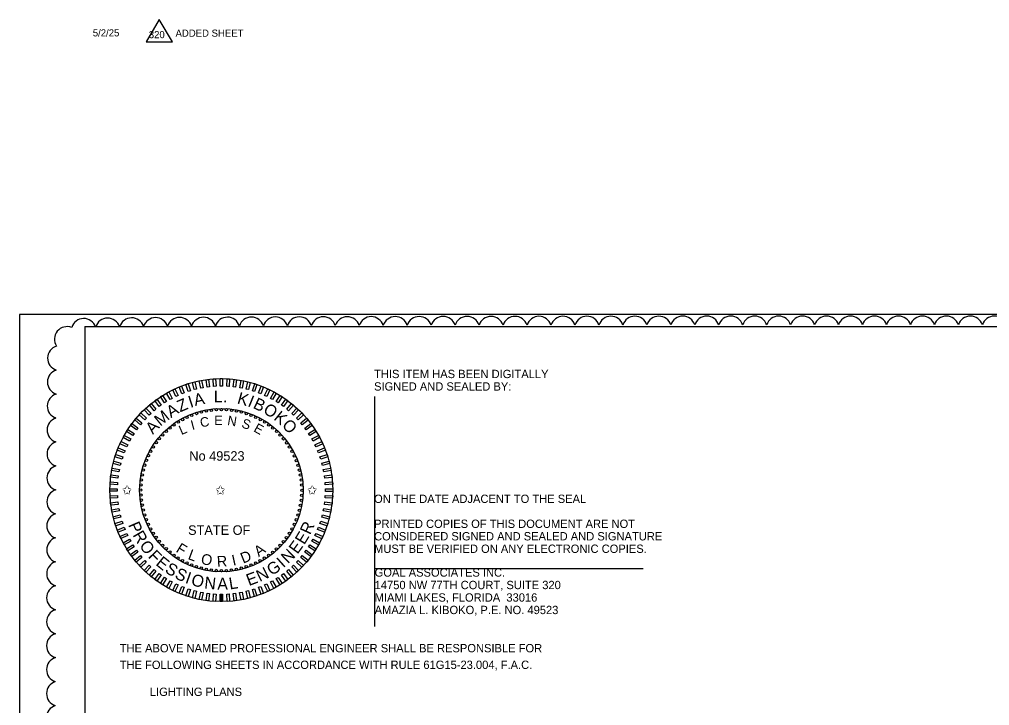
# Model space of a CAD drawing. Extents: x -811.2 to -755.6, y -2295.2 to -2235.1.
# Drawn here: x -783.91 to -775.75, y -2275.63 to -2269.86 of the extents above; entities that cross this region are included whole.
import ezdxf

# ---------------------------------------------------------------- set-up
doc = ezdxf.new("R2010")
doc.units = 0
for name, color, linetype in [('Cloud_dp', 7, 'Continuous'), ('Logo_dp', 7, 'Continuous'), ('NonPlottingEle_dp', 7, 'Continuous'), ('PlotBorder_dp', 7, 'Continuous'), ('ScratchEle_dp', 7, 'Continuous'), ('SheetBorder_dp', 7, 'Continuous'), ('TextMinor', 7, 'Continuous'), ('TextMisc', 7, 'Continuous')]:
    doc.layers.add(name, color=color, linetype=linetype)

msp = doc.modelspace()

# ---------------------------------------------------------------- linework, layer by layer
at = {"layer": 'Cloud_dp'}
msp.add_lwpolyline([(-782.7321, -2269.8629), (-782.8398, -2270.051), (-782.6192, -2270.051)], close=True, dxfattribs=at)
for centre, start, end in [((-783.3652, -2272.4837), 18.59454, 163.59454), ((-783.1638, -2272.4805), 18.21421, 163.21421), ((-782.9624, -2272.4783), 18.04696, 163.04696), ((-782.7609, -2272.4766), 17.94666, 162.94666), ((-782.5594, -2272.4751), 17.87787, 162.87787), ((-782.3579, -2272.4739), 17.82689, 162.82689), ((-782.1564, -2272.4728), 17.78716, 162.78716), ((-781.9548, -2272.4719), 17.75505, 162.75505), ((-781.7533, -2272.471), 17.72841, 162.72841), ((-781.5518, -2272.4702), 17.70584, 162.70584), ((-781.3502, -2272.4696), 17.6864, 162.6864), ((-781.1487, -2272.4689), 17.66942, 162.66942), ((-780.9472, -2272.4684), 17.65443, 162.65443), ((-780.7456, -2272.4678), 17.64106, 162.64106), ((-780.5441, -2272.4674), 17.62905, 162.62905), ((-780.3425, -2272.4669), 17.61817, 162.61817), ((-780.141, -2272.4665), 17.60826, 162.60826), ((-779.9394, -2272.4662), 17.59919, 162.59919), ((-779.7379, -2272.4658), 17.59084, 162.59084), ((-779.5364, -2272.4655), 17.58312, 162.58312), ((-779.3348, -2272.4653), 17.57595, 162.57595), ((-779.1333, -2272.465), 17.56928, 162.56928), ((-778.9317, -2272.4648), 17.56305, 162.56305), ((-778.7302, -2272.4646), 17.55721, 162.55721), ((-778.5286, -2272.4644), 17.55172, 162.55172), ((-778.3271, -2272.4642), 17.54655, 162.54655), ((-778.1255, -2272.464), 17.54167, 162.54167), ((-777.924, -2272.4639), 17.53705, 162.53705), ((-777.7224, -2272.4638), 17.53267, 162.53267), ((-777.5209, -2272.4637), 17.52851, 162.52851), ((-777.3194, -2272.4636), 17.52455, 162.52455), ((-777.1178, -2272.4635), 17.52079, 162.52079), ((-776.9163, -2272.4634), 17.51719, 162.51719), ((-776.7147, -2272.4634), 17.51375, 162.51375), ((-776.5132, -2272.4633), 17.51046, 162.51046), ((-776.3116, -2272.4633), 17.50731, 162.50731), ((-776.1101, -2272.4633), 17.50428, 162.50428), ((-775.9085, -2272.4633), 17.50138, 162.50138), ((-775.707, -2272.4633), 17.5, 162.5), ((-783.5053, -2272.5521), 68.43954, 213.43954), ((-783.563, -2272.7115), 106.80445, 251.80445), ((-783.565, -2272.9129), 107.04367, 252.04367), ((-783.5664, -2273.1144), 107.15618, 252.15618), ((-783.5675, -2273.3159), 107.22533, 252.22533), ((-783.5684, -2273.5174), 107.27338, 252.27338), ((-783.5691, -2273.719), 107.30928, 252.30928), ((-783.5697, -2273.9205), 107.33743, 252.33743), ((-783.5703, -2274.122), 107.36027, 252.36027), ((-783.5707, -2274.3236), 107.37928, 252.37928), ((-783.5711, -2274.5251), 107.39543, 252.39543), ((-783.5715, -2274.7267), 107.40937, 252.40937), ((-783.5717, -2274.9282), 107.42156, 252.42156), ((-783.572, -2275.1297), 107.43234, 252.43234), ((-783.5722, -2275.3313), 107.44197, 252.44197), ((-783.5724, -2275.5328), 107.45063, 252.45063), ((-783.5726, -2275.7344), 107.45847, 252.45847)]:
    msp.add_arc(centre, 0.1057, start, end, dxfattribs=at)
at = {"layer": 'Logo_dp'}
for p, q in [((-782.2178, -2274.759), (-782.218, -2274.6965)), ((-782.2078, -2274.759), (-782.208, -2274.6965)), ((-782.1978, -2274.759), (-782.198, -2274.6965))]:
    msp.add_line(p, q, dxfattribs=at)
for points in [[(-782.4685, -2272.9862), (-782.4877, -2272.9924), (-782.507, -2272.933), (-782.4878, -2272.9268)], [(-782.4156, -2272.9714), (-782.4351, -2272.9765), (-782.4506, -2272.916), (-782.4311, -2272.911)], [(-782.3618, -2272.9601), (-782.3816, -2272.9638), (-782.3933, -2272.9025), (-782.3735, -2272.8987)], [(-782.3074, -2272.9521), (-782.3274, -2272.9546), (-782.3352, -2272.8927), (-782.3152, -2272.8902)], [(-782.2526, -2272.9476), (-782.2727, -2272.9488), (-782.2767, -2272.8865), (-782.2565, -2272.8852)], [(-782.1976, -2272.9465), (-782.2178, -2272.9465), (-782.2178, -2272.884), (-782.1976, -2272.884)], [(-782.1427, -2272.9488), (-782.1629, -2272.9476), (-782.1589, -2272.8853), (-782.1388, -2272.8865)], [(-782.088, -2272.9547), (-782.1081, -2272.9521), (-782.1002, -2272.8902), (-782.0802, -2272.8927)], [(-782.0338, -2272.9639), (-782.0537, -2272.9601), (-782.042, -2272.8988), (-782.0221, -2272.9026)], [(-781.9803, -2272.9765), (-781.9999, -2272.9715), (-781.9844, -2272.911), (-781.9648, -2272.916)], [(-781.9277, -2272.9925), (-781.9469, -2272.9862), (-781.9276, -2272.9268), (-781.9084, -2272.9331)], [(-782.6204, -2273.0498), (-782.6381, -2273.0595), (-782.6682, -2273.0048), (-782.6505, -2272.9951)], [(-782.5712, -2273.0254), (-782.5894, -2273.034), (-782.616, -2272.9775), (-782.5978, -2272.9689)], [(-782.5205, -2273.0042), (-782.5392, -2273.0116), (-782.5622, -2272.9536), (-782.5434, -2272.9461)], [(-781.8762, -2273.0117), (-781.895, -2273.0042), (-781.872, -2272.9462), (-781.8532, -2272.9536)], [(-781.826, -2273.0341), (-781.8443, -2273.0255), (-781.8177, -2272.969), (-781.7994, -2272.9776)], [(-781.7773, -2273.0596), (-781.795, -2273.0499), (-781.7649, -2272.9952), (-781.7473, -2273.0049)], [(-782.7139, -2273.1076), (-782.7302, -2273.1195), (-782.7669, -2273.069), (-782.7506, -2273.0571)], [(-782.6681, -2273.0772), (-782.6851, -2273.0881), (-782.7186, -2273.0353), (-782.7015, -2273.0245)], [(-781.7303, -2273.0882), (-781.7474, -2273.0773), (-781.7139, -2273.0246), (-781.6969, -2273.0354)], [(-781.6852, -2273.1196), (-781.7016, -2273.1077), (-781.6649, -2273.0572), (-781.6485, -2273.0691)], [(-782.8387, -2273.2151), (-782.8525, -2273.2298), (-782.898, -2273.1871), (-782.8842, -2273.1723)], [(-782.7994, -2273.1767), (-782.8141, -2273.1905), (-782.8568, -2273.145), (-782.8421, -2273.1311)], [(-782.7577, -2273.1408), (-782.7733, -2273.1537), (-782.8131, -2273.1055), (-782.7975, -2273.0927)], [(-781.6422, -2273.1538), (-781.6578, -2273.1409), (-781.618, -2273.0928), (-781.6024, -2273.1057)], [(-781.6014, -2273.1906), (-781.6161, -2273.1768), (-781.5734, -2273.1313), (-781.5586, -2273.1451)], [(-781.563, -2273.2299), (-781.5768, -2273.2152), (-781.5313, -2273.1725), (-781.5175, -2273.1872)], [(-782.8755, -2273.2559), (-782.8884, -2273.2714), (-782.9365, -2273.2316), (-782.9237, -2273.2161)], [(-781.5271, -2273.2716), (-781.54, -2273.256), (-781.4919, -2273.2162), (-781.479, -2273.2318)], [(-782.9412, -2273.344), (-782.952, -2273.3611), (-783.0047, -2273.3276), (-782.9939, -2273.3106)], [(-782.9097, -2273.2989), (-782.9216, -2273.3153), (-782.9721, -2273.2786), (-782.9603, -2273.2622)], [(-781.4939, -2273.3154), (-781.5058, -2273.2991), (-781.4553, -2273.2624), (-781.4434, -2273.2787)], [(-781.4635, -2273.3612), (-781.4744, -2273.3442), (-781.4216, -2273.3107), (-781.4108, -2273.3278)], [(-782.9952, -2273.4397), (-783.0038, -2273.458), (-783.0603, -2273.4314), (-783.0517, -2273.4131)], [(-782.9697, -2273.391), (-782.9794, -2273.4087), (-783.0341, -2273.3786), (-783.0244, -2273.361)], [(-781.4361, -2273.4089), (-781.4458, -2273.3912), (-781.3911, -2273.3611), (-781.3814, -2273.3788)], [(-781.4117, -2273.4582), (-781.4203, -2273.4399), (-781.3638, -2273.4133), (-781.3552, -2273.4316)], [(-783.0176, -2273.4899), (-783.0251, -2273.5087), (-783.0831, -2273.4857), (-783.0757, -2273.4669)], [(-781.3905, -2273.5089), (-781.3979, -2273.4901), (-781.3399, -2273.4671), (-781.3324, -2273.4859)], [(-783.0528, -2273.594), (-783.0578, -2273.6136), (-783.1183, -2273.5981), (-783.1133, -2273.5785)], [(-783.0369, -2273.5414), (-783.0431, -2273.5606), (-783.1025, -2273.5413), (-783.0963, -2273.5221)], [(-781.3725, -2273.5608), (-781.3787, -2273.5416), (-781.3193, -2273.5223), (-781.3131, -2273.5415)], [(-781.3577, -2273.6138), (-781.3628, -2273.5942), (-781.3023, -2273.5787), (-781.2973, -2273.5982)], [(-783.0654, -2273.6475), (-783.0692, -2273.6674), (-783.1306, -2273.6557), (-783.1268, -2273.6358)], [(-781.3464, -2273.6675), (-781.3502, -2273.6477), (-781.2888, -2273.636), (-781.285, -2273.6558)], [(-783.0747, -2273.7017), (-783.0772, -2273.7218), (-783.1391, -2273.7139), (-783.1366, -2273.6939)], [(-781.3384, -2273.7219), (-781.3409, -2273.7019), (-781.279, -2273.6941), (-781.2765, -2273.7141)], [(-783.0828, -2273.8113), (-783.0828, -2273.8315), (-783.1453, -2273.8315), (-783.1453, -2273.8113)], [(-783.0805, -2273.7564), (-783.0817, -2273.7765), (-783.1441, -2273.7726), (-783.1428, -2273.7525)], [(-781.3339, -2273.7767), (-781.3351, -2273.7566), (-781.2728, -2273.7527), (-781.2716, -2273.7728)], [(-781.3328, -2273.8317), (-781.3328, -2273.8115), (-781.2703, -2273.8115), (-781.2703, -2273.8317)], [(-783.0818, -2273.8663), (-783.0805, -2273.8864), (-783.1428, -2273.8904), (-783.1441, -2273.8702)], [(-781.3351, -2273.8866), (-781.3339, -2273.8665), (-781.2716, -2273.8704), (-781.2728, -2273.8905)], [(-783.0772, -2273.9211), (-783.0747, -2273.9411), (-783.1366, -2273.9489), (-783.1392, -2273.9289)], [(-783.0693, -2273.9755), (-783.0655, -2273.9953), (-783.1268, -2274.007), (-783.1306, -2273.9872)], [(-781.3502, -2273.9955), (-781.3464, -2273.9756), (-781.2851, -2273.9873), (-781.2889, -2274.0072)], [(-781.341, -2273.9413), (-781.3384, -2273.9213), (-781.2765, -2273.9291), (-781.279, -2273.9491)], [(-783.0579, -2274.0293), (-783.0529, -2274.0488), (-783.1133, -2274.0643), (-783.1184, -2274.0448)], [(-781.3628, -2274.049), (-781.3578, -2274.0294), (-781.2973, -2274.045), (-781.3023, -2274.0645)], [(-783.0432, -2274.0822), (-783.0369, -2274.1014), (-783.0963, -2274.1207), (-783.1025, -2274.1015)], [(-783.0251, -2274.1342), (-783.0177, -2274.1529), (-783.0758, -2274.1759), (-783.0832, -2274.1571)], [(-781.398, -2274.1531), (-781.3906, -2274.1343), (-781.3325, -2274.1573), (-781.3399, -2274.1761)], [(-781.3788, -2274.1016), (-781.3725, -2274.0824), (-781.3131, -2274.1017), (-781.3194, -2274.1209)], [(-783.0039, -2274.1849), (-782.9953, -2274.2031), (-783.0518, -2274.2297), (-783.0604, -2274.2114)], [(-781.4204, -2274.2033), (-781.4118, -2274.185), (-781.3553, -2274.2116), (-781.3639, -2274.2299)], [(-782.9795, -2274.2341), (-782.9698, -2274.2518), (-783.0245, -2274.2819), (-783.0342, -2274.2642)], [(-782.9521, -2274.2818), (-782.9413, -2274.2988), (-782.994, -2274.3323), (-783.0048, -2274.3152)], [(-781.4745, -2274.299), (-781.4636, -2274.2819), (-781.4109, -2274.3154), (-781.4217, -2274.3324)], [(-781.4459, -2274.252), (-781.4362, -2274.2343), (-781.3815, -2274.2644), (-781.3912, -2274.2821)], [(-782.9217, -2274.3276), (-782.9099, -2274.3439), (-782.9604, -2274.3806), (-782.9722, -2274.3643)], [(-782.8885, -2274.3714), (-782.8757, -2274.387), (-782.9238, -2274.4268), (-782.9366, -2274.4112)], [(-781.5401, -2274.3871), (-781.5272, -2274.3716), (-781.4791, -2274.4114), (-781.492, -2274.4269)], [(-781.5059, -2274.3441), (-781.494, -2274.3277), (-781.4435, -2274.3644), (-781.4554, -2274.3808)], [(-782.8527, -2274.4131), (-782.8388, -2274.4278), (-782.8844, -2274.4705), (-782.8982, -2274.4558)], [(-782.8142, -2274.4524), (-782.7995, -2274.4662), (-782.8423, -2274.5117), (-782.857, -2274.4979)], [(-781.6162, -2274.4663), (-781.6015, -2274.4525), (-781.5588, -2274.498), (-781.5735, -2274.5119)], [(-781.5769, -2274.4279), (-781.5631, -2274.4132), (-781.5176, -2274.456), (-781.5314, -2274.4707)], [(-782.7734, -2274.4892), (-782.7579, -2274.5021), (-782.7977, -2274.5502), (-782.8132, -2274.5373)], [(-782.7304, -2274.5234), (-782.7141, -2274.5353), (-782.7508, -2274.5858), (-782.7671, -2274.5739)], [(-782.6853, -2274.5549), (-782.6682, -2274.5657), (-782.7017, -2274.6184), (-782.7187, -2274.6076)], [(-781.7475, -2274.5658), (-781.7305, -2274.555), (-781.697, -2274.6077), (-781.7141, -2274.6185)], [(-781.7017, -2274.5354), (-781.6854, -2274.5235), (-781.6487, -2274.5741), (-781.665, -2274.5859)], [(-781.6579, -2274.5022), (-781.6423, -2274.4894), (-781.6025, -2274.5375), (-781.6181, -2274.5503)], [(-782.6383, -2274.5834), (-782.6206, -2274.5931), (-782.6507, -2274.6478), (-782.6684, -2274.6381)], [(-782.5896, -2274.6089), (-782.5713, -2274.6175), (-782.5979, -2274.674), (-782.6162, -2274.6654)], [(-782.5394, -2274.6313), (-782.5206, -2274.6388), (-782.5436, -2274.6968), (-782.5624, -2274.6894)], [(-781.8952, -2274.6388), (-781.8764, -2274.6314), (-781.8534, -2274.6895), (-781.8722, -2274.6969)], [(-781.8445, -2274.6176), (-781.8262, -2274.609), (-781.7996, -2274.6655), (-781.8179, -2274.6741)], [(-781.7952, -2274.5932), (-781.7775, -2274.5835), (-781.7474, -2274.6382), (-781.7651, -2274.6479)], [(-782.4879, -2274.6506), (-782.4687, -2274.6568), (-782.488, -2274.7162), (-782.5072, -2274.7099)], [(-782.4353, -2274.6665), (-782.4157, -2274.6715), (-782.4313, -2274.732), (-782.4508, -2274.727)], [(-782.3818, -2274.6791), (-782.362, -2274.6829), (-782.3737, -2274.7442), (-782.3935, -2274.7405)], [(-782.3276, -2274.6884), (-782.3076, -2274.6909), (-782.3154, -2274.7528), (-782.3354, -2274.7503)], [(-782.2729, -2274.6942), (-782.2528, -2274.6954), (-782.2567, -2274.7578), (-782.2768, -2274.7565)], [(-782.218, -2274.6965), (-782.1978, -2274.6965), (-782.1978, -2274.759), (-782.218, -2274.759)], [(-782.163, -2274.6954), (-782.1429, -2274.6942), (-782.139, -2274.7565), (-782.1591, -2274.7578)], [(-782.1082, -2274.6909), (-782.0882, -2274.6884), (-782.0804, -2274.7503), (-782.1004, -2274.7529)], [(-782.0539, -2274.6829), (-782.034, -2274.6792), (-782.0223, -2274.7405), (-782.0422, -2274.7443)], [(-782.0001, -2274.6716), (-781.9805, -2274.6666), (-781.965, -2274.727), (-781.9845, -2274.7321)], [(-781.9471, -2274.6569), (-781.9279, -2274.6506), (-781.9086, -2274.71), (-781.9278, -2274.7162)]]:
    msp.add_lwpolyline(points, close=True, dxfattribs=at)
for centre in [(-782.4166, -2273.177), (-782.3757, -2273.1652), (-782.3342, -2273.1559), (-782.2922, -2273.1493), (-782.2498, -2273.1453), (-782.2072, -2273.144), (-782.1647, -2273.1454), (-782.1223, -2273.1495), (-782.0803, -2273.1561), (-782.0388, -2273.1655), (-781.9979, -2273.1774), (-782.5703, -2273.2492), (-782.5337, -2273.2276), (-782.4958, -2273.2083), (-782.4567, -2273.1914), (-781.9579, -2273.1918), (-781.9189, -2273.2088), (-781.8809, -2273.2281), (-781.8443, -2273.2498), (-782.6712, -2273.3273), (-782.6392, -2273.2991), (-782.6056, -2273.2731), (-781.8092, -2273.2738), (-781.7755, -2273.2999), (-781.7436, -2273.328), (-782.7556, -2273.4228), (-782.7295, -2273.3892), (-782.7013, -2273.3573), (-781.7136, -2273.3582), (-781.6855, -2273.3901), (-781.6594, -2273.4238), (-782.8012, -2273.4946), (-782.7795, -2273.458), (-781.6355, -2273.459), (-781.6139, -2273.4956), (-782.8375, -2273.5716), (-782.8206, -2273.5325), (-781.5946, -2273.5336), (-781.5777, -2273.5726), (-782.8639, -2273.6525), (-782.852, -2273.6116), (-781.5633, -2273.6127), (-781.5515, -2273.6536), (-782.8799, -2273.736), (-782.8732, -2273.694), (-781.5422, -2273.6951), (-781.5356, -2273.7372), (-782.8853, -2273.8209), (-782.8839, -2273.7784), (-781.5316, -2273.7795), (-781.5303, -2273.8221), (-782.884, -2273.8635), (-782.88, -2273.9059), (-781.5358, -2273.907), (-781.5317, -2273.8646), (-782.8734, -2273.9479), (-782.8641, -2273.9894), (-781.5518, -2273.9905), (-781.5425, -2273.949), (-782.8523, -2274.0303), (-782.8379, -2274.0704), (-781.5781, -2274.0714), (-781.5637, -2274.0314), (-782.821, -2274.1094), (-782.8018, -2274.1474), (-781.6144, -2274.1484), (-781.5951, -2274.1105), (-782.7801, -2274.184), (-782.7562, -2274.2193), (-781.6601, -2274.2202), (-781.6361, -2274.185), (-782.7302, -2274.2529), (-782.7021, -2274.2849), (-782.672, -2274.315), (-781.7445, -2274.3157), (-781.7143, -2274.2857), (-781.6862, -2274.2538), (-782.6401, -2274.3431), (-782.6065, -2274.3693), (-782.5713, -2274.3932), (-781.8453, -2274.3938), (-781.8101, -2274.3699), (-781.7764, -2274.3439), (-782.5347, -2274.4149), (-782.4968, -2274.4343), (-782.4577, -2274.4512), (-782.4177, -2274.4656), (-782.3768, -2274.4776), (-782.3353, -2274.4869), (-782.0814, -2274.4871), (-782.0399, -2274.4778), (-781.999, -2274.466), (-781.9589, -2274.4516), (-781.9199, -2274.4347), (-781.8819, -2274.4154), (-782.2933, -2274.4936), (-782.2509, -2274.4976), (-782.2078, -2274.499), (-782.1658, -2274.4977), (-782.1235, -2274.4937)]:
    msp.add_circle(centre, 0.01, dxfattribs=at)
at = {"layer": 'NonPlottingEle_dp'}
for radius in [0.9375, 0.6875]:
    msp.add_circle((-782.2078, -2273.8215), radius, dxfattribs=at)
at = {"layer": 'PlotBorder_dp'}
msp.add_lwpolyline([(-783.9062, -2282.9457), (-767.4062, -2282.9457), (-767.4062, -2272.3457), (-783.9062, -2272.3457)], close=True, dxfattribs=at)
at = {"layer": 'ScratchEle_dp'}
for p, q in [((-780.9186, -2273.0346), (-780.9186, -2274.9693)), ((-780.9186, -2274.4793), (-778.6618, -2274.4793))]:
    msp.add_line(p, q, dxfattribs=at)
at = {"layer": 'SheetBorder_dp'}
for q in [(-783.3562, -2282.8457), (-767.9562, -2272.4457)]:
    msp.add_line((-783.3562, -2272.4457), q, dxfattribs=at)

# ---------------------------------------------------------------- texts
at = {"layer": 'Cloud_dp'}
msp.add_text('320', height=0.05998, rotation=0, dxfattribs=at).set_placement((-782.8179, -2270.0208))
at = {"layer": 'Logo_dp'}
for s, rotation, p in [('I', 14.81888, (-782.4534, -2273.3163)), ('C', 8.98261, (-782.3808, -2273.2936)), ('E', 359.96623, (-782.2681, -2273.2747)), ('N', 350.64643, (-782.1612, -2273.2733)), ('S', 341.03996, (-782.0441, -2273.2921)), ('L', 23.30524, (-782.544, -2273.3592)), ('E', 331.16864, (-781.9426, -2273.3247))]:
    msp.add_text(s, height=0.08, rotation=rotation, dxfattribs=at).set_placement(p)
for p in [(-783.0428, -2273.8595), (-782.2581, -2273.8595), (-781.4862, -2273.8595)]:
    msp.add_text('✩', height=0.08, dxfattribs=at).set_placement(p)
at = {"layer": 'TextMinor'}
for s, p in [('5/2/25', (-783.2889, -2270.006)), ('ADDED SHEET', (-782.593, -2270.0084))]:
    msp.add_text(s, height=0.06, dxfattribs=at).set_placement(p)
at = {"layer": 'TextMisc'}
for s, height, p in [('THIS ITEM HAS BEEN DIGITALLY', 0.07, (-780.9235, -2272.8795)), ('SIGNED AND SEALED BY:', 0.07, (-780.9235, -2272.9845)), ('No 49523', 0.08, (-782.4768, -2273.5743)), ('ON THE DATE ADJACENT TO THE SEAL', 0.07, (-780.9235, -2273.9295)), ('PRINTED COPIES OF THIS DOCUMENT ARE NOT ', 0.07, (-780.9235, -2274.1395)), ('STATE OF', 0.08, (-782.4875, -2274.1977)), ('CONSIDERED SIGNED AND SEALED AND SIGNATURE ', 0.07, (-780.9235, -2274.2445)), ('MUST BE VERIFIED ON ANY ELECTRONIC COPIES.', 0.07, (-780.9235, -2274.3495)), ('GOAL ASSOCIATES INC.', 0.07, (-780.9186, -2274.5493)), ('14750 NW 77TH COURT, SUITE 320', 0.07, (-780.9186, -2274.6543)), ('MIAMI LAKES, FLORIDA  33016', 0.07, (-780.9186, -2274.7593)), ('AMAZIA L. KIBOKO, P.E. NO. 49523', 0.07, (-780.9186, -2274.8643)), ('THE ABOVE NAMED PROFESSIONAL ENGINEER SHALL BE RESPONSIBLE FOR ', 0.07, (-783.0626, -2275.1855)), ('THE FOLLOWING SHEETS IN ACCORDANCE WITH RULE 61G15-23.004, F.A.C.', 0.07, (-783.0626, -2275.3255)), ('LIGHTING PLANS', 0.07, (-782.8089, -2275.5525))]:
    msp.add_text(s, height=height, dxfattribs=at).set_placement(p)
for s, height, rotation, p in [('A', 0.1, 11.91844, (-782.4286, -2273.1146)), ('L', 0.1, 359.96623, (-782.2714, -2273.0842)), ('K', 0.1, 344.27273, (-782.0807, -2273.0914)), ('Z', 0.1, 23.30524, (-782.5548, -2273.1682)), ('I', 0.1, 17.68363, (-782.4679, -2273.1306)), ('.', 0.1, 353.78581, (-782.1947, -2273.0813)), ('I', 0.1, 337.77772, (-781.9921, -2273.1133)), ('B', 0.1, 334.48695, (-781.9482, -2273.1286)), ('M', 0.1, 39.30005, (-782.7212, -2273.2889)), ('A', 0.1, 31.46601, (-782.6322, -2273.2168)), ('O', 0.1, 327.82385, (-781.8635, -2273.1671)), ('K', 0.1, 321.0594, (-781.7739, -2273.2243)), ('A', 0.1, 46.80938, (-782.7835, -2273.3574)), ('O', 0.1, 314.20329, (-781.7043, -2273.2819)), ('P', 0.1, 293.19548, (-782.9935, -2274.1131)), ('R', 0.1, 65.28865, (-781.4614, -2274.2024)), ('R', 0.1, 300.25949, (-782.9566, -2274.199)), ('E', 0.1, 58.61694, (-781.5106, -2274.2864)), ('O', 0.1, 307.26617, (-782.9025, -2274.2908)), ('F', 0.09, 328.53399, (-782.5962, -2274.3368)), ('A', 0.09, 35.54629, (-781.8934, -2274.3861)), ('N', 0.1, 44.34211, (-781.6479, -2274.445)), ('E', 0.1, 53.99864, (-781.5679, -2274.3651)), ('F', 0.1, 314.20329, (-782.8291, -2274.3833)), ('E', 0.1, 321.0594, (-782.7657, -2274.4469)), ('L', 0.09, 339.48752, (-782.495, -2274.3998)), ('O', 0.09, 348.08156, (-782.3856, -2274.4404)), ('R', 0.09, 3.10738, (-782.2434, -2274.4666)), ('I', 0.09, 12.52485, (-782.1092, -2274.4575)), ('D', 0.09, 22.22228, (-782.0251, -2274.4406)), ('I', 0.1, 41.83906, (-781.6873, -2274.4792)), ('S', 0.1, 327.82385, (-782.6895, -2274.5074)), ('N', 0.1, 26.0618, (-781.8846, -2274.5954)), ('G', 0.1, 34.11362, (-781.7834, -2274.5452)), ('S', 0.1, 334.48695, (-782.6064, -2274.5588)), ('I', 0.1, 341.03996, (-782.5178, -2274.6001)), ('O', 0.1, 344.27273, (-782.4687, -2274.6177)), ('N', 0.1, 353.78581, (-782.3543, -2274.6476)), ('A', 0.1, 359.96623, (-782.242, -2274.6586)), ('L', 0.1, 8.98261, (-782.1363, -2274.6578)), ('E', 0.1, 20.51248, (-781.9761, -2274.6287))]:
    msp.add_text(s, height=height, rotation=rotation, dxfattribs=at).set_placement(p)

doc.saveas('drawing.dxf')
